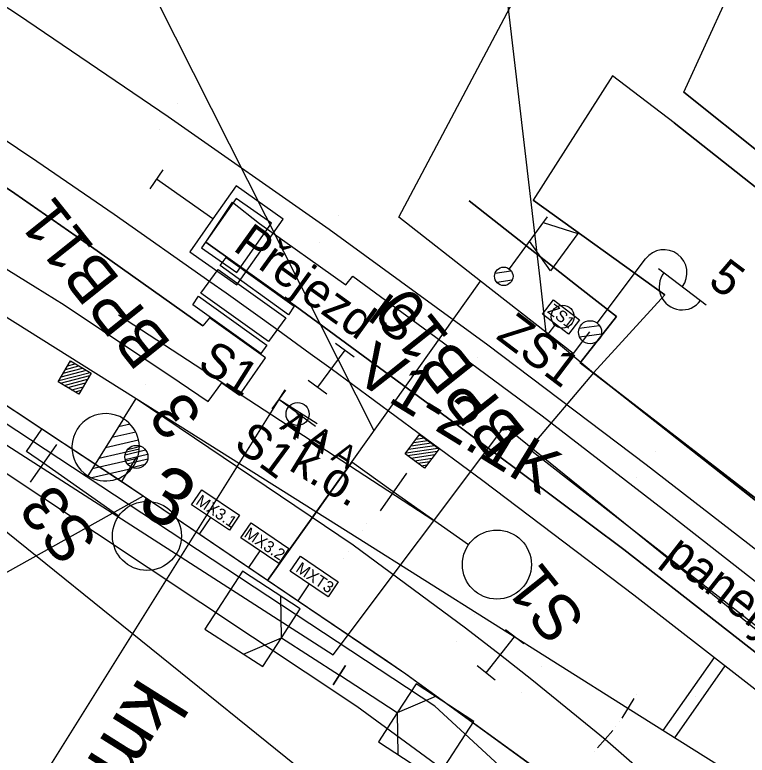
# Model space of a CAD drawing. Extents: x -621145 to -620023, y -1122866 to -1121971.
# Drawn here: x -620327.81 to -620295.98, y -1122683.59 to -1122651.4 of the extents above; entities that cross this region are included whole.
import ezdxf

# ---------------------------------------------------------------- set-up
doc = ezdxf.new("R2010")
doc.units = 0
for name, color, linetype in [('060601_EOV', 7, 'Continuous'), ('060604_ROZVODY_SEE', 7, 'Continuous'), ('POPIS KABELOVÉ TRASY', 7, 'Continuous'), ('PS 06-14-01_trasa_sdělovací_nové', 7, 'Continuous'), ('SEE', 7, 'Continuous'), ('SO 06', 7, 'Continuous'), ('SSZT', 7, 'Continuous'), ('UZEMNĚNÍ', 7, 'Continuous'), ('Vrstva 1', 7, 'Continuous'), ('Vrstva 12', 7, 'Continuous'), ('Vrstva 14', 7, 'Continuous'), ('Vrstva 16', 7, 'Continuous'), ('Vrstva 2', 7, 'Continuous'), ('Vrstva 25', 7, 'Continuous'), ('Vrstva 27', 7, 'Continuous'), ('Vrstva 3', 7, 'Continuous'), ('Vrstva 33', 7, 'Continuous'), ('Vrstva 4', 7, 'Continuous'), ('Vrstva 51', 7, 'Continuous'), ('Vrstva 53', 7, 'Continuous'), ('Vrstva 55', 7, 'Continuous'), ('Vrstva 6', 7, 'Continuous'), ('Vrstva 62', 7, 'Continuous'), ('Vrstva 7', 7, 'Continuous')]:
    doc.layers.add(name, color=color, linetype=linetype)

msp = doc.modelspace()

# ---------------------------------------------------------------- linework, layer by layer
at = {"layer": '060601_EOV'}
for p, q in [((-620319.299, -1122673.255), (-620319.788, -1122673.977)), ((-620317.154, -1122674.7), (-620317.648, -1122675.428)), ((-620315.01, -1122676.145), (-620315.508, -1122676.879))]:
    msp.add_line(p, q, dxfattribs=at)
msp.add_lwpolyline([(-620235.16, -1122712.242), (-620240.174, -1122718.342), (-620243.025, -1122715.998), (-620248.321, -1122722.765), (-620259.889, -1122713.575), (-620277.713, -1122700.902), (-620282.346, -1122705.302), (-620297.82, -1122689.49), (-620304.222, -1122684.862), (-620310.815, -1122680.061), (-620322.228, -1122672.322), (-620343.182, -1122658.459), (-620368.499, -1122642.897), (-620411.557, -1122614.916), (-620424.156, -1122607.087), (-620443.525, -1122595.005), (-620456.111, -1122587.123), (-620447.823, -1122572.959), (-620450.948, -1122571.455), (-620470.592, -1122561.479), (-620499.61, -1122545.574), (-620522.038, -1122531.471), (-620538.89, -1122521.208), (-620599.215, -1122483.216)], dxfattribs=at)
for points in [[(-620319.683, -1122672.048), (-620318.035, -1122673.159), (-620318.475, -1122673.81), (-620320.123, -1122672.7)], [(-620317.539, -1122673.493), (-620315.891, -1122674.603), (-620316.33, -1122675.255), (-620317.978, -1122674.145)], [(-620315.395, -1122674.938), (-620313.747, -1122676.048), (-620314.186, -1122676.7), (-620315.834, -1122675.59)]]:
    msp.add_lwpolyline(points, close=True, dxfattribs=at)
at = {"layer": '060604_ROZVODY_SEE'}
msp.add_line((-620304.307, -1122664.856), (-620304.643, -1122665.284), dxfattribs=at)
for points in [[(-620243.025, -1122715.998), (-620248.321, -1122722.765), (-620259.889, -1122713.575), (-620277.713, -1122700.902), (-620282.346, -1122705.302), (-620297.82, -1122689.49), (-620304.222, -1122684.862), (-620310.815, -1122680.061), (-620316.822, -1122675.988), (-620322.228, -1122672.322), (-620326.634, -1122669.408), (-620343.182, -1122658.459), (-620368.499, -1122642.897), (-620411.557, -1122614.916), (-620424.156, -1122607.087), (-620443.525, -1122595.005), (-620444.244, -1122596.151)], [(-620316.822, -1122675.988), (-620307.569, -1122662.984), (-620311.113, -1122660.198), (-620304.112, -1122646.984), (-620307.038, -1122645.433), (-620340.053, -1122630.257)], [(-620302.826, -1122665.182), (-620303.546, -1122666.133), (-620307.569, -1122662.984)]]:
    msp.add_lwpolyline(points, dxfattribs=at)
msp.add_lwpolyline([(-620304.396, -1122663.798), (-620303.263, -1122664.665), (-620303.741, -1122665.29), (-620304.874, -1122664.423)], close=True, dxfattribs=at)
at = {"layer": 'POPIS KABELOVÉ TRASY'}
for points in [[(-620312.196, -1122669.486), (-620323.97, -1122646.126), (-620330.292, -1122641.833)], [(-620322.228, -1122672.322), (-620336.532, -1122680.315), (-620342.855, -1122676.022)]]:
    msp.add_lwpolyline(points, dxfattribs=at)
at = {"layer": 'PS 06-14-01_trasa_sdělovací_nové'}
msp.add_lwpolyline([(-620248.321, -1122722.765), (-620259.889, -1122713.575), (-620277.711, -1122700.887), (-620282.346, -1122705.302), (-620297.82, -1122689.49), (-620310.815, -1122680.061), (-620322.228, -1122672.322), (-620343.182, -1122658.459), (-620368.499, -1122642.897), (-620411.557, -1122614.916), (-620456.111, -1122587.123), (-620544.953, -1122530.859), (-620538.89, -1122521.208), (-620538.89, -1122521.208), (-620538.89, -1122521.208)], dxfattribs=at)
at = {"layer": 'SEE'}
for points in [[(-620244.518, -1122694.296), (-620246.547, -1122692.66), (-620267.469, -1122718.6), (-620268.222, -1122719.534), (-620284.407, -1122704.62), (-620304.333, -1122686.26), (-620309.55, -1122681.453), (-620327.714, -1122669.483), (-620362.834, -1122646.339), (-620390.254, -1122629.02), (-620411.934, -1122614.961), (-620423.125, -1122608.012), (-620468.337, -1122579.91), (-620468.337, -1122579.91), (-620460.94, -1122568.103), (-620517.418, -1122533.032), (-620535.001, -1122522.477), (-620545.407, -1122539.454), (-620611.375, -1122497.696)], [(-620340.053, -1122630.257), (-620307.038, -1122645.433), (-620304.995, -1122662.882), (-620304.721, -1122665.223), (-620302.66, -1122666.96), (-620305.446, -1122670.265), (-620283.044, -1122687.742), (-620274.947, -1122694.711), (-620269.357, -1122688.084), (-620267.489, -1122689.555)]]:
    msp.add_lwpolyline(points, dxfattribs=at)
at = {"layer": 'SO 06'}
msp.add_lwpolyline([(-620298.23, -1122690.946), (-620299.598, -1122691.249), (-620312.943, -1122681.47), (-620333.337, -1122667.924), (-620356.709, -1122652.765), (-620357.203, -1122652.946), (-620412.63, -1122616.604), (-620445.655, -1122595.98), (-620446.002, -1122596.548)], dxfattribs=at)
at = {"layer": 'SSZT'}
msp.add_line((-620309.595, -1122673.397), (-620323.304, -1122664.466), dxfattribs=at)
msp.add_lwpolyline([(-620879.238, -1122313.316), (-620842.993, -1122336.61), (-620835.049, -1122343.251), (-620812.66, -1122358.949), (-620764.902, -1122389.752), (-620688.594, -1122438.969), (-620596.981, -1122496.725), (-620576.744, -1122509.484), (-620506.746, -1122556.123), (-620447.293, -1122593.619), (-620363.271, -1122647.563), (-620313.966, -1122679.218), (-620306.51, -1122669.289), (-620273.137, -1122696.274), (-620258.422, -1122709.142), (-620248.072, -1122696.094)], dxfattribs=at)
at = {"layer": 'UZEMNĚNÍ'}
msp.add_line((-620304.307, -1122664.856), (-620304.643, -1122665.284), dxfattribs=at)
msp.add_lwpolyline([(-620302.826, -1122665.182), (-620303.546, -1122666.133), (-620307.569, -1122662.984), (-620311.113, -1122660.198), (-620304.112, -1122646.984), (-620307.038, -1122645.433), (-620340.053, -1122630.257)], dxfattribs=at)
at = {"layer": 'Vrstva 1'}
for p, q in [((-620323.174, -1122671.696), (-620326.634, -1122669.408)), ((-620322.521, -1122670.619), (-620323.174, -1122671.696)), ((-620313.165, -1122670.848), (-620316.822, -1122675.988)), ((-620311.36, -1122672.145), (-620313.165, -1122670.848))]:
    msp.add_line(p, q, dxfattribs=at)
for points in [[(-620326.634, -1122669.408), (-620343.182, -1122658.459), (-620368.499, -1122642.897), (-620411.557, -1122614.916), (-620436.755, -1122599.259), (-620456.111, -1122587.123)], [(-620348.688, -1122637.935), (-620341.5, -1122642.47), (-620339.854, -1122643.512), (-620333.156, -1122647.798), (-620327.653, -1122651.408), (-620321.139, -1122655.817), (-620314.146, -1122660.717), (-620307.245, -1122665.745), (-620300.366, -1122670.953), (-620293.063, -1122676.601), (-620287.47, -1122681.018), (-620281.24, -1122686.066), (-620276.174, -1122690.251), (-620272.417, -1122693.451), (-620267.757, -1122697.544), (-620266.519, -1122698.689), (-620262.242, -1122702.65), (-620256.103, -1122708.562), (-620249.907, -1122714.621), (-620245.657, -1122718.815), (-620238.557, -1122725.547), (-620230.199, -1122732.623), (-620229.854, -1122732.906)], [(-620339.555, -1122649.372), (-620332.789, -1122653.783), (-620326.854, -1122657.769), (-620323.491, -1122660.075), (-620319.328, -1122662.995), (-620318.623, -1122663.494), (-620316.382, -1122665.099), (-620314.967, -1122666.125), (-620314.061, -1122666.783), (-620307.461, -1122671.648), (-620300.906, -1122676.615), (-620294.546, -1122681.556)], [(-620339.555, -1122649.372), (-620332.789, -1122653.783), (-620326.854, -1122657.769), (-620323.491, -1122660.075), (-620319.328, -1122662.995), (-620318.623, -1122663.494), (-620316.382, -1122665.099), (-620314.967, -1122666.125), (-620314.061, -1122666.783), (-620307.461, -1122671.648), (-620300.906, -1122676.615), (-620294.546, -1122681.556)], [(-620347.616, -1122652.305), (-620342.456, -1122655.575), (-620322.526, -1122668.083), (-620312.925, -1122674.13), (-620301.163, -1122681.549), (-620292.126, -1122687.227), (-620282.992, -1122692.997), (-620276.394, -1122697.25), (-620266.758, -1122703.956), (-620255.894, -1122712.191)], [(-620322.526, -1122668.083), (-620313.097, -1122674.436), (-620308.214, -1122678.053), (-620306.7, -1122679.227), (-620305.337, -1122680.296), (-620302.152, -1122682.886), (-620294.636, -1122689.472), (-620288.443, -1122695.324), (-620284.812, -1122699.019), (-620282.778, -1122701.089), (-620280.313, -1122703.598), (-620275.628, -1122708.447), (-620262.902, -1122721.469), (-620255.487, -1122728.261), (-620248.439, -1122734.187)], [(-620326.567, -1122670.898), (-620327.304, -1122670.379), (-620326.634, -1122669.408)], [(-620316.822, -1122675.988), (-620322.228, -1122672.322), (-620323.174, -1122671.696)], [(-620288.271, -1122699.248), (-620297.82, -1122689.49), (-620304.222, -1122684.862), (-620310.815, -1122680.061), (-620311.612, -1122679.521), (-620316.822, -1122675.988)]]:
    msp.add_lwpolyline(points, dxfattribs=at)
at = {"layer": 'Vrstva 12'}
msp.add_lwpolyline([(-620293.461, -1122674.083), (-620303.242, -1122666.538), (-620301.662, -1122664.522), (-620303.242, -1122663.293), (-620308.054, -1122659.497), (-620303.242, -1122663.293), (-620301.662, -1122664.522), (-620303.242, -1122666.538), (-620293.461, -1122674.083)], dxfattribs=at)
at = {"layer": 'Vrstva 14'}
for points in [[(-620346.591, -1122650.915), (-620335.3, -1122658.037), (-620326.919, -1122663.23), (-620325.66, -1122664.016), (-620320.659, -1122667.355), (-620319.405, -1122668.214), (-620318.806, -1122667.396), (-620318.045, -1122667.942), (-620316.915, -1122666.32), (-620319.344, -1122664.58), (-620319.636, -1122664.917), (-620324.475, -1122661.491), (-620327.8, -1122659.174), (-620333.678, -1122655.247), (-620340.478, -1122650.803), (-620347.325, -1122646.469)], [(-620347.325, -1122646.469), (-620340.478, -1122650.803), (-620333.678, -1122655.247), (-620327.8, -1122659.174), (-620324.475, -1122661.491), (-620319.636, -1122664.917)]]:
    msp.add_lwpolyline(points, dxfattribs=at)
at = {"layer": 'Vrstva 16'}
msp.add_lwpolyline([(-620268.767, -1122698.19), (-620269.667, -1122699.332), (-620273.339, -1122696.067), (-620280.591, -1122690.258), (-620287.721, -1122684.651), (-620288.092, -1122685.04), (-620293.259, -1122680.96), (-620301.343, -1122674.65), (-620308.503, -1122669.28), (-620315.629, -1122664.052), (-620319.501, -1122661.293), (-620318.339, -1122659.55), (-620317.166, -1122660.468), (-620313.424, -1122663.148), (-620313.111, -1122662.768), (-620309.78, -1122665.216), (-620304.891, -1122668.836), (-620299.292, -1122673.151), (-620286.498, -1122683.168), (-620286.771, -1122683.508), (-620280.456, -1122688.482), (-620273.255, -1122694.212), (-620268.767, -1122698.19)], dxfattribs=at)
at = {"layer": 'Vrstva 2'}
for p, q in [((-620325.608, -1122666.82), (-620325.019, -1122666.667)), ((-620325.514, -1122666.66), (-620325.178, -1122666.573)), ((-620325.419, -1122666.5), (-620325.338, -1122666.479)), ((-620325.891, -1122667.3), (-620324.539, -1122666.95)), ((-620325.796, -1122667.139), (-620324.699, -1122666.856)), ((-620325.702, -1122666.98), (-620324.859, -1122666.762)), ((-620325.817, -1122667.416), (-620324.547, -1122667.088)), ((-620325.657, -1122667.51), (-620324.642, -1122667.248)), ((-620325.497, -1122667.604), (-620324.736, -1122667.408)), ((-620325.337, -1122667.699), (-620324.83, -1122667.568)), ((-620325.177, -1122667.793), (-620324.924, -1122667.727)), ((-620323.078, -1122668.963), (-620322.526, -1122668.083)), ((-620323.078, -1122668.963), (-620324.634, -1122671.442)), ((-620322.789, -1122669.204), (-620323.299, -1122669.32)), ((-620322.552, -1122669.54), (-620323.585, -1122669.776)), ((-620322.426, -1122669.9), (-620323.871, -1122670.23)), ((-620310.469, -1122669.993), (-620309.867, -1122669.904)), ((-620310.358, -1122669.844), (-620310.016, -1122669.793)), ((-620310.248, -1122669.695), (-620310.165, -1122669.683)), ((-620325.993, -1122670.08), (-620327.141, -1122671.717)), ((-620322.395, -1122670.283), (-620324.157, -1122670.686)), ((-620322.904, -1122670.3), (-620322.326, -1122670.161)), ((-620310.801, -1122670.44), (-620309.42, -1122670.236)), ((-620310.69, -1122670.29), (-620309.569, -1122670.126)), ((-620310.58, -1122670.142), (-620309.718, -1122670.015)), ((-620323.011, -1122670.531), (-620322.124, -1122670.319)), ((-620323.007, -1122670.736), (-620322.037, -1122670.503)), ((-620310.74, -1122670.563), (-620309.443, -1122670.372)), ((-620310.591, -1122670.674), (-620309.554, -1122670.521)), ((-620323.292, -1122673.194), (-620326.567, -1122670.898)), ((-620322.477, -1122670.692), (-620324.443, -1122671.141)), ((-620322.919, -1122670.921), (-620322.03, -1122670.707)), ((-620322.718, -1122671.078), (-620322.139, -1122670.939)), ((-620310.442, -1122670.785), (-620309.664, -1122670.67)), ((-620310.293, -1122670.895), (-620309.775, -1122670.819)), ((-620322.731, -1122671.14), (-620324.457, -1122671.534)), ((-620310.144, -1122671.006), (-620309.886, -1122670.968)), ((-620310.786, -1122671.326), (-620311.934, -1122672.964)), ((-620308.085, -1122674.441), (-620311.36, -1122672.145)), ((-620300.897, -1122681.126), (-620301.429, -1122681.972)), ((-620301.822, -1122682.51), (-620302.482, -1122683.262))]:
    msp.add_line(p, q, dxfattribs=at)
for points in [[(-620325.389, -1122666.449), (-620324.485, -1122666.982), (-620325.018, -1122667.887), (-620325.922, -1122667.354)], [(-620325.389, -1122666.449), (-620324.485, -1122666.982), (-620325.018, -1122667.887), (-620325.922, -1122667.354)], [(-620310.212, -1122669.647), (-620309.37, -1122670.274), (-620309.996, -1122671.116), (-620310.839, -1122670.49)], [(-620310.212, -1122669.647), (-620309.37, -1122670.274), (-620309.996, -1122671.116), (-620310.839, -1122670.49)]]:
    msp.add_lwpolyline(points, close=True, dxfattribs=at)
for points in [[(-620322.526, -1122668.083), (-620312.925, -1122674.13), (-620301.163, -1122681.549)], [(-620322.526, -1122668.083), (-620313.097, -1122674.436), (-620308.214, -1122678.053), (-620306.7, -1122679.227), (-620305.337, -1122680.296), (-620302.152, -1122682.886)]]:
    msp.add_lwpolyline(points, dxfattribs=at)
for centre, radius in [((-620322.521, -1122670.619), 0.5), ((-620322.064, -1122674.055), 1.5), ((-620306.856, -1122675.302), 1.5)]:
    msp.add_circle(centre, radius, dxfattribs=at)
for centre, start, end in [((-620323.861, -1122670.199), 57.653, 238.1225), ((-620323.857, -1122670.202), 237.9073, 57.8682)]:
    msp.add_arc(centre, 1.463, start, end, dxfattribs=at)
at = {"layer": 'Vrstva 25'}
for p, q in [((-620302.503, -1122664.801), (-620300.389, -1122662.012)), ((-620299.831, -1122662.435), (-620297.759, -1122664.005)), ((-620304.037, -1122664.496), (-620303.957, -1122664.556)), ((-620303.274, -1122665.028), (-620302.403, -1122664.908)), ((-620303.259, -1122665.404), (-620302.311, -1122665.273))]:
    msp.add_line(p, q, dxfattribs=at)
for centre in [(-620303.997, -1122664.526), (-620302.805, -1122665.2)]:
    msp.add_circle(centre, 0.5, dxfattribs=at)
for centre, start, end in [((-620299.592, -1122662.616), 322.8473, 142.8473), ((-620298.803, -1122663.23), 142.1447, 323.5498)]:
    msp.add_arc(centre, 1, start, end, dxfattribs=at)
at = {"layer": 'Vrstva 27'}
msp.add_line((-620315.56, -1122668.731), (-620315.474, -1122668.783), dxfattribs=at)
msp.add_circle((-620315.517, -1122668.757), 0.5, dxfattribs=at)
at = {"layer": 'Vrstva 3'}
for p, q in [((-620313.87, -1122665.681), (-620313.065, -1122666.275)), ((-620313.87, -1122665.681), (-620313.065, -1122666.275)), ((-620313.468, -1122665.978), (-620314.654, -1122667.588)), ((-620313.468, -1122665.978), (-620314.654, -1122667.588)), ((-620315.057, -1122667.291), (-620314.252, -1122667.885)), ((-620315.057, -1122667.291), (-620314.252, -1122667.885)), ((-620305.689, -1122678.749), (-620306.476, -1122678.132)), ((-620307.317, -1122680.014), (-620306.083, -1122678.44)), ((-620306.924, -1122680.322), (-620307.711, -1122679.705))]:
    msp.add_line(p, q, dxfattribs=at)
at = {"layer": 'Vrstva 33'}
for p, q in [((-620304.673, -1122660.188), (-620306.319, -1122662.447)), ((-620306.93, -1122662.634), (-620306.243, -1122662.526)), ((-620306.86, -1122663.028), (-620306.186, -1122662.922))]:
    msp.add_line(p, q, dxfattribs=at)
msp.add_lwpolyline([(-620304.85, -1122660.43), (-620303.343, -1122660.91), (-620304.521, -1122662.526), (-620305.439, -1122661.239)], dxfattribs=at)
msp.add_circle((-620306.555, -1122662.771), 0.401, dxfattribs=at)
at = {"layer": 'Vrstva 4'}
for points in [[(-620318.882, -1122662.306), (-620318.619, -1122661.946), (-620315.665, -1122664.074), (-620315.919, -1122664.443), (-620318.882, -1122662.306)], [(-620318.974, -1122662.471), (-620316.033, -1122664.574), (-620316.787, -1122665.599), (-620319.718, -1122663.504), (-620318.974, -1122662.471)], [(-620319.328, -1122662.995), (-620318.623, -1122663.494), (-620316.382, -1122665.099)], [(-620320.077, -1122664.008), (-620319.828, -1122663.627), (-620316.857, -1122665.763), (-620317.118, -1122666.125), (-620320.077, -1122664.008)]]:
    msp.add_lwpolyline(points, dxfattribs=at)
at = {"layer": 'Vrstva 51'}
msp.add_lwpolyline([(-620319.501, -1122661.293), (-620315.629, -1122664.052), (-620308.503, -1122669.28), (-620301.343, -1122674.65), (-620293.259, -1122680.96), (-620288.092, -1122685.04), (-620287.721, -1122684.651), (-620280.591, -1122690.258), (-620273.339, -1122696.067), (-620269.667, -1122699.332)], dxfattribs=at)
at = {"layer": 'Vrstva 53'}
for p, q in [((-620298.73, -1122654.76), (-620296.23, -1122649.3)), ((-620301.83, -1122654.06), (-620305.28, -1122659.46)), ((-620299.15, -1122656.1), (-620301.83, -1122654.06)), ((-620298.73, -1122654.76), (-620265, -1122681.82)), ((-620299.15, -1122656.1), (-620261.22, -1122686.17)), ((-620299.56, -1122663.58), (-620305.28, -1122659.46)), ((-620299.56, -1122663.58), (-620302.66, -1122666.96)), ((-620267.81, -1122694.49), (-620302.66, -1122666.96)), ((-620309.9, -1122688.62), (-620334.71, -1122668.63))]:
    msp.add_line(p, q, dxfattribs=at)
at = {"layer": 'Vrstva 55'}
for p, q in [((-620298.73, -1122654.76), (-620296.23, -1122649.3)), ((-620301.83, -1122654.06), (-620305.28, -1122659.46)), ((-620299.15, -1122656.1), (-620301.83, -1122654.06)), ((-620265, -1122681.82), (-620298.73, -1122654.76)), ((-620261.22, -1122686.17), (-620299.15, -1122656.1)), ((-620305.28, -1122659.46), (-620299.56, -1122663.58)), ((-620299.56, -1122663.58), (-620302.66, -1122666.96)), ((-620302.66, -1122666.96), (-620267.81, -1122694.49)), ((-620309.9, -1122688.62), (-620334.71, -1122668.63))]:
    msp.add_line(p, q, dxfattribs=at)
at = {"layer": 'Vrstva 6'}
for p, q in [((-620316.071, -1122667.703), (-620316.605, -1122668.549)), ((-620316.041, -1122667.724), (-620316.635, -1122668.528)), ((-620316.338, -1122668.126), (-620330.777, -1122691.249)), ((-620314.663, -1122669.182), (-620316.338, -1122668.126)), ((-620314.744, -1122669.301), (-620316.338, -1122668.126))]:
    msp.add_line(p, q, dxfattribs=at)
at = {"layer": 'Vrstva 62'}
for p, q in [((-620320.748, -1122655.238), (-620320.748, -1122655.238)), ((-620321.529, -1122656.396), (-620321.529, -1122656.396)), ((-620313.738, -1122660.134), (-620313.738, -1122660.134)), ((-620314.553, -1122661.3), (-620314.553, -1122661.3)), ((-620306.783, -1122665.199), (-620306.783, -1122665.199)), ((-620307.677, -1122666.314), (-620307.677, -1122666.314)), ((-620322.142, -1122667.49), (-620322.142, -1122667.49)), ((-620322.91, -1122668.677), (-620322.91, -1122668.677)), ((-620299.944, -1122670.391), (-620299.944, -1122670.391)), ((-620300.788, -1122671.515), (-620300.788, -1122671.515)), ((-620312.692, -1122673.835), (-620312.692, -1122673.835)), ((-620312.536, -1122673.534), (-620312.536, -1122673.534)), ((-620313.315, -1122674.727), (-620313.315, -1122674.727)), ((-620313.502, -1122675.037), (-620313.502, -1122675.037)), ((-620307.809, -1122677.461), (-620307.809, -1122677.461)), ((-620308.618, -1122678.645), (-620308.618, -1122678.645)), ((-620306.275, -1122678.641), (-620306.275, -1122678.641)), ((-620307.124, -1122679.813), (-620307.124, -1122679.813)), ((-620304.896, -1122679.744), (-620304.896, -1122679.744)), ((-620305.778, -1122680.848), (-620305.778, -1122680.848)), ((-620300.779, -1122680.954), (-620300.779, -1122680.954)), ((-620301.547, -1122682.144), (-620301.547, -1122682.144)), ((-620301.687, -1122682.347), (-620301.687, -1122682.347)), ((-620302.618, -1122683.425), (-620302.618, -1122683.425))]:
    msp.add_line(p, q, dxfattribs=at)
at = {"layer": 'Vrstva 7'}
for p, q in [((-620321.367, -1122658.144), (-620321.941, -1122658.962)), ((-620319.198, -1122660.276), (-620321.654, -1122658.553)), ((-620316.217, -1122678.48), (-620313.701, -1122680.114)), ((-620299.627, -1122682.514), (-620297.403, -1122679.337)), ((-620313.429, -1122679.695), (-620313.973, -1122680.533)), ((-620313.973, -1122680.533), (-620313.429, -1122679.695)), ((-620299.118, -1122682.834), (-620296.928, -1122679.705)), ((-620311.185, -1122681.748), (-620313.701, -1122680.114)), ((-620298.228, -1122681.039), (-620298.228, -1122681.039))]:
    msp.add_line(p, q, dxfattribs=at)
for points in [[(-620319.198, -1122660.276), (-620320.202, -1122661.707), (-620318.155, -1122663.142), (-620316.147, -1122660.28), (-620318.194, -1122658.845), (-620319.198, -1122660.276)], [(-620318.939, -1122660.457), (-620319.69, -1122661.528), (-620318.154, -1122662.605), (-620316.65, -1122660.46), (-620318.186, -1122659.383), (-620318.939, -1122660.457)], [(-620316.217, -1122678.48), (-620315.4, -1122677.222), (-620317.915, -1122675.587), (-620319.55, -1122678.103), (-620317.034, -1122679.737), (-620316.217, -1122678.48)], [(-620317.874, -1122679.192), (-620316.217, -1122678.48), (-620316.24, -1122676.676)], [(-620311.185, -1122681.748), (-620312.002, -1122683.006), (-620309.487, -1122684.641), (-620307.852, -1122682.125), (-620310.368, -1122680.491), (-620311.185, -1122681.748)], [(-620309.528, -1122681.036), (-620311.185, -1122681.748), (-620311.162, -1122683.552)]]:
    msp.add_lwpolyline(points, dxfattribs=at)

# ---------------------------------------------------------------- texts
at = {"layer": '060601_EOV'}
for s, p in [('MX3.1', (-620319.98, -1122672.649)), ('MX3.2', (-620317.879, -1122674.065)), ('MXT3', (-620315.637, -1122675.576))]:
    msp.add_text(s, height=0.5, rotation=326.029, dxfattribs=at).set_placement(p)
at = {"layer": '060604_ROZVODY_SEE'}
msp.add_text('ZS1', height=0.5, rotation=322.5799, dxfattribs=at).set_placement((-620304.691, -1122664.322))
at = {"layer": 'Vrstva 16'}
msp.add_text('panely', height=1.5, rotation=321.941, dxfattribs=at).set_placement((-620299.672, -1122675.04))
at = {"layer": 'Vrstva 2'}
msp.add_text('3', height=2.5, rotation=327.8878, dxfattribs=at).set_placement((-620322.587, -1122672.896))
at = {"layer": 'Vrstva 25'}
for s, rotation, p in [('5', 322.8473, (-620297.732, -1122663.1)), ('ZS1', 322.8711, (-620306.939, -1122665.446))]:
    msp.add_text(s, height=1.5, rotation=rotation, dxfattribs=at).set_placement(p)
at = {"layer": 'Vrstva 27'}
for s, height, p in [('V1-2.1K', 2, (-620313.166, -1122667.242)), ('k.o.', 1.5, (-620315.951, -1122671.158))]:
    msp.add_text(s, height=height, rotation=328.4879, dxfattribs=at).set_placement(p)
at = {"layer": 'Vrstva 3'}
for s, height, rotation, p in [('BPB11', 2, 128.542, (-620320.953, -1122665.723)), ('IS', 1.5, 323.6053, (-620312.548, -1122664.624)), ('BPB10', 2, 128.542, (-620305.526, -1122669.616)), ('3', 2, 128.542, (-620319.589, -1122668.814)), ('S3', 2, 128.542, (-620324.117, -1122674.24)), ('S1', 2, 128.542, (-620302.932, -1122677.683))]:
    msp.add_text(s, height=height, rotation=rotation, dxfattribs=at).set_placement(p)
at = {"layer": 'Vrstva 4'}
msp.add_text('Přejezd', height=1.5, rotation=324.2373, dxfattribs=at).set_placement((-620318.371, -1122661.606))
at = {"layer": 'Vrstva 6'}
for s, height, rotation, p in [('S1', 1.5, 327.7824, (-620319.93, -1122666.741)), ('  A A ', 1, 323.6053, (-620316.931, -1122668.931)), ('  A A A ', 1, 327.7824, (-620316.871, -1122668.972)), ('S1', 1.5, 323.6053, (-620318.352, -1122670.182)), ('km 63,371', 2.5, 237.7824, (-620322.376, -1122680.13))]:
    msp.add_text(s, height=height, rotation=rotation, dxfattribs=at).set_placement(p)

doc.saveas('drawing.dxf')
